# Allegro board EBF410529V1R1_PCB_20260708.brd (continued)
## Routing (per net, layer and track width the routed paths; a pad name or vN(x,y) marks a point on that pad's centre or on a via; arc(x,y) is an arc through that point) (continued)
RMII1_MDIN2: length 63.3
  TOP w0.107: v1(81.5,36.23) 81.86,35.87 81.86,33.08 81.8,33.02 U8.7
  BOTTOM w0.107: v1(81.5,36.23) 81.1,36.63 81.1,37.44 79.65,38.89 70.95,38.89 66.42,43.41 66.42,49.6 66.77,49.95 66.77,50.89 66.42,51.24 66.42,56.67 68.66,58.9 68.66,63.88 75.08,70.3 79.93,70.3 81.48,71.86 81.48,73.05 81.63,73.19 J7.6
RMII1_MDIN3: length 61.6
  TOP w0.107: U8.10 80.6,33.02 80.66,33.08 80.66,36.08 v1(80.51,36.22)
  BOTTOM w0.107: J7.9 77.82,72.97 78,73.15 78.61,73.15 78.93,72.84 78.93,71.59 78.42,71.07 74.74,71.07 67.85,64.19 67.85,59.31 65.38,56.84 65.38,43.16 70.42,38.12 79.01,38.12 80.1,37.02 80.1,36.63 v1(80.51,36.22)
RMII1_MDIP0: length 67
  TOP w0.107: v1(84.01,37.03) 84.41,36.64 84.41,33.94 84.14,33.67 84.14,33.08 84.2,33.02 U8.1
  BOTTOM w0.107: J7.2 86.71,73.13 86.84,73 86.84,71.76 86.02,70.94 85.13,70.94 84.29,70.1 82.54,70.1 80.92,68.47 75.84,68.47 70.49,63.12 70.49,58.12 68.34,55.98 68.34,52.51 68.83,52.02 68.83,48.87 68.34,48.38 68.34,44.56 72,40.9 80.97,40.9 83.89,37.98 83.89,37.14 83.99,37.03 v1(84.01,37.03)
RMII1_MDIP1: length 72.4
  TOP w0.107: v1(83.01,37.03) 83.41,36.63 83.41,33.94 82.93,33.46 82.93,33.09 83,33.02 U8.4
  BOTTOM w0.107: v1(83.01,37.03) 82.89,37.16 82.89,37.58 80.43,40.04 71.6,40.04 67.57,44.06 67.57,48.98 67.97,49.38 67.97,51.51 67.57,51.91 67.57,56.3 69.71,58.44 69.71,63.44 75.52,69.25 80.44,69.25 82.11,70.92 83.74,70.92 84.31,71.48 84.31,72.86 83.06,74.11 83.06,75.37 83.44,75.74 85.27,75.74 85.45,75.56 85.45,74.27 85.24,74.07 84.38,74.07 84.17,74.28 J7.4
RMII1_MDIP2: length 63.4
  TOP w0.107: U8.6 82.2,33.02 82.14,33.08 82.14,36.4 v1(81.51,37.03)
  BOTTOM w0.107: v1(81.51,37.03) 81.49,37.03 81.39,37.14 81.39,37.56 79.77,39.17 71.06,39.17 66.71,43.53 66.71,49.48 67.06,49.83 67.06,51 66.71,51.35 66.71,56.55 68.94,58.78 68.94,63.76 75.2,70.02 80.05,70.02 81.77,71.74 81.77,72.91 81.96,73.1 82.73,73.1 82.9,72.93 J7.5
RMII1_MDIP3: length 61.7
  TOP w0.107: v1(80.51,37.03) 80.94,36.6 80.94,33.08 81,33.02 U8.9
  BOTTOM w0.107: J7.8 78.84,74.5 78.84,73.33 79.21,72.95 79.21,71.47 78.53,70.79 74.85,70.79 68.13,64.07 68.13,59.19 65.66,56.72 65.66,43.28 70.54,38.4 79.13,38.4 80.49,37.03 v1(80.51,37.03)
RMII1_VDD10: length 34.4
  TOP w0.203: v1(85.95,31.19) 85.68,30.92 U8.38 ; U8.8 v1(81.4,33.23) ; U8.3 v1(83.4,33.23) ; C56.1 79.83,26.11 80.6,26.88 U8.21
  TOP w0.254: C56.1 78.19,26.37 v1(78.19,26.86)
  ART03 w0.254: v1(86.2,20.19) 86.2,21.8 81.14,26.86 v1(78.19,26.86)
  BOTTOM w0.254: v1(78.19,26.86) 79.01,26.86 79.55,27.41 79.55,30.2 79.04,30.71 79.04,32.25 79.55,32.76 80.92,32.76 v1(81.4,33.23) 81.91,32.72 C53.1 C55.1 82.9,32.73 v1(83.4,33.23) 83.9,32.73 85.36,32.73 85.95,32.13 v1(85.95,31.19)
ROUT1: length 42.2
  TOP w0.203: v1(47.52,67.26) 53.04,67.26 54.18,68.4 54.18,70.89 53.03,72.03 C82.2
  ART03 w0.203: v1(24.69,61.43) 25.42,61.43 25.7,61.72 25.7,63.95 26.16,64.41 26.16,65.3 28.25,67.39 31.42,67.39 31.93,66.88 35.56,66.88 36.75,65.68 45.8,65.68 47.37,67.26 v1(47.52,67.26)
  BOTTOM w0.107: U9.11 24.69,61.41 v1(24.69,61.43)
ROUT2: length 20
  BOTTOM w0.254: U9.14 26.46,62.06 26.46,64.21 27.19,64.93 27.19,65.43 26.83,65.79 19.91,65.79 19.18,66.52 17.48,66.52 17.12,66.88 17.12,71.25 17.37,71.5 C211.1
RS232_R1IN: length 13.5
  TOP w0.254: U33.13 55.17,17.02 54.51,16.36 54.51,8.71 51.97,6.17 J24.4
RS232_R1OUT: length 86.8
  TOP w0.254: U33.12 v1(55.01,15.74)
  ART03 w0.254: v1(55.01,15.74) 57.43,13.32 57.43,11.02 57.94,10.52 66.4,10.52 71.58,5.33 116.18,5.33 117.2,6.35 132.2,6.35 132.99,5.56 J27.1
RS232_R2IN: length 19.2
  TOP w0.254: U33.8 v1(52.18,11.94)
  ART03 w0.254: J24.1 61.99,4.65 54.41,4.65 53.52,5.54 53.52,7.09 52.18,8.43 v1(52.18,11.94)
RS232_R2OUT: length 78.5
  TOP w0.254: U33.9 v1(55.01,11.94)
  ART03 w0.254: J28.1 123.72,3.25 118.75,3.25 118.41,2.92 67.94,2.92 66.33,4.53 66.33,7.33 65.23,8.43 56.54,8.43 55.01,9.96 v1(55.01,11.94)
RS232_T1IN: length 87.9
  TOP w0.254: U33.11 v1(55.01,14.48)
  ART03 w0.254: J27.2 131.65,3.28 131.65,4.9 130.99,5.56 118.21,5.56 117.27,4.62 70.79,4.62 65.99,9.42 57.23,9.42 56.36,10.29 56.36,13.13 v1(55.01,14.48)
RS232_T1OUT: length 21.2
  TOP w0.254: J24.6 45.97,7.67 50.62,7.67 53.7,10.74 53.7,17.77 54.2,18.28 U33.14
RS232_T2IN: length 81.9
  TOP w0.254: U33.10 v1(55.01,13.2)
  ART03 w0.254: J28.2 123.94,0.94 118.87,0.94 117.63,2.18 67.01,2.18 65.25,3.94 65.25,6.89 64.64,7.49 56.13,7.49 54.15,9.47 54.15,12.34 v1(55.01,13.2)
RS232_T2OUT: length 10
  TOP w0.254: U33.7 v1(52.18,13.2)
  ART03 w0.254: J24.3 53.01,8.82 53.01,12.37 v1(52.18,13.2)
RS485_1_3V3: length 12.8
  TOP w0.254: D41.2 41.63,12.86 41.63,20.22 41.03,20.82 U36.8
  TOP w0.381: U36.8 v1(39.18,20.82)
  BOTTOM w0.381: v1(39.18,20.82) 39.05,20.69 C198.1 L16.2
RS485_1_A: length 26.7
  TOP w0.254: R211.2 38.47,14.77 38.93,14.31 DN1.2 38.23,11.02 38.23,9.91 40.64,7.5 40.64,4.57 40.08,4.01 36.98,4.01 36.43,4.57 36.43,5.54 35.92,6.05 J31.2 ; R211.2 38.23,15.74 38.23,18.24 38.58,18.59 39.27,18.59 39.58,18.28 U36.6 ; R211.2 R213.1
RS485_1_B: length 25.6
  TOP w0.254: U36.7 39.67,19.55 39.29,19.18 38.53,19.18 37.72,18.36 37.72,15.74 R211.1 ; R214.1 R211.1 ; R211.1 37.47,14.77 37.02,14.31 DN1.1 37.72,11.02 37.72,9.7 40.13,7.29 40.13,4.9 39.75,4.52 37.32,4.52 36.94,4.9 36.94,5.54 37.45,6.05 J31.1
RS485_1_DIR: length 75
  TOP w0.107: J3.180 61.19,65.61 v1(61.2,65.61) ; v1(55.56,65.61) 56.13,65.03 56.13,53.66 53.29,50.82 53.29,27.23 48.13,22.07 37.57,22.07 36.69,21.19 v1(36.69,19.55) U36.2 34.39,19.55 34.16,19.33 34.16,18.47 34.34,18.29 35.43,18.29 U36.3
  BOTTOM w0.107: v1(55.56,65.61) 56.47,64.69 60.28,64.69 v1(61.2,65.61)
  BOTTOM w0.254: R212.1 36.69,20.04 v1(36.69,19.55)
RS485_2_3V3: length 12.9
  TOP w0.254: D42.2 49.28,12.89 49.28,20.29 48.75,20.82 U37.8
  TOP w0.381: U37.8 v1(46.84,20.82)
  BOTTOM w0.381: v1(46.84,20.82) 46.71,20.69 C199.1 L17.2
RS485_2_A: length 39.3
  TOP w0.254: R216.2 46.09,14.77 46.55,14.31 DN2.2 45.85,11.02 45.85,10.41 42.75,7.31 42.75,3.42 41.96,2.64 29.54,2.64 28.81,3.37 28.81,5.54 28.3,6.05 J31.4 ; R216.2 R215.1 ; R216.2 45.85,15.74 45.85,18.23 46.28,18.66 47.1,18.66 47.48,18.28 U37.6
RS485_2_B: length 38.3
  TOP w0.254: J31.3 29.83,6.05 29.32,5.54 29.32,3.65 29.83,3.15 41.73,3.15 42.24,3.65 42.24,7.52 45.34,10.62 45.34,11.02 DN2.1 44.64,14.31 45.09,14.77 R216.1 ; R218.1 R216.1 ; R216.1 45.34,15.74 45.34,18.44 46.07,19.17 47.11,19.17 47.49,19.55 U37.7
RS485_2_DIR: length 64.5
  TOP w0.107: v1(44.35,19.55) 44.37,19.53 44.37,18.44 44.22,18.28 U37.3 ; v1(44.35,19.55) U37.2 ; v1(44.35,19.55) 44.35,21.4 44.56,21.62 48.36,21.62 53.77,27.03 53.77,50.75 56.46,53.44 56.46,65.51 v1(56.56,65.61) ; J3.178 60.69,65.12 v1(60.2,65.61)
  BOTTOM w0.107: v1(56.56,65.61) 57.04,65.13 59.71,65.13 v1(60.2,65.61)
  BOTTOM w0.254: R217.1 44.35,20.04 v1(44.35,19.55)
RTC_INT: length 137
  TOP w0.107: v1(59.2,65.61) 59.99,66.41 71.24,66.41 71.69,65.95 J3.222 ; v1(20.48,18.54) 21.46,17.55 26.37,17.55 27.72,18.9 27.72,21.67 28.47,22.42 47.94,22.42 52.83,27.32 52.83,50.85 55.8,53.82 55.8,64.79 55.46,65.13 55.04,65.13 v1(54.56,65.61)
  BOTTOM w0.107: D18.2 9.85,47.45 9.64,47.24 R156.2 10.59,46.99 10.95,47.35 15.65,47.35 17.09,45.9 17.09,43.95 19.99,41.05 19.99,19.28 20.48,18.79 v1(20.48,18.54) ; v1(54.56,65.61) 54.97,66.02 58.79,66.02 v1(59.2,65.61)
SAI1_LRCK_M0: length 6.4
  TOP w0.132: v1(22.26,60.44) 22.76,60.94 22.76,61.7 23.19,62.13 J3.36
  BOTTOM w0.132: v1(22.26,60.44) 22.84,60.44 U9.7
SAI1_MCLK_M0: length 15.6
  TOP w0.132: J3.34 22.69,62.26 22.26,61.83 v1(22.26,61.44)
  BOTTOM w0.132: U9.1 24.37,55.22 21.49,55.22 20.83,55.88 20.83,60.77 21.04,60.99 21.81,60.99 v1(22.26,61.44)
SAI1_SCLK_M0: length 8
  TOP w0.132: J3.38 23.69,62.02 23.25,61.58 23.25,60.33 22.81,59.89 22.81,58.88 v1(23.26,58.44)
  BOTTOM w0.132: U9.5 24.94,58.34 24.46,57.86 23.93,57.86 23.35,58.44 v1(23.26,58.44)
SAI1_SDI0_M0: length 4.4
  TOP w0.107: v1(24.08,60.75) 24.08,61.41 24.69,62.03 J3.42
  BOTTOM w0.107: U9.8 23.91,60.28 23.91,60.59 v1(24.08,60.75)
SAI1_SDO2_M0: length 6.8
  TOP w0.107: J3.40 24.19,61.96 23.65,61.42 23.65,59.82 23.26,59.44 v1(23.26,59.41)
  BOTTOM w0.107: v1(23.26,59.41) 23.26,59.11 23.98,58.39 24.36,58.39 U9.6
SARADC_IN3: length 109.8
  TOP w0.107: R207.1 86.51,16.35 86.51,12.14 v1(86.74,11.91) ; v1(49.19,59.25) 48.21,60.23 42.76,60.23 41.32,61.67 40.44,61.67 40.19,61.92 v1(40.19,62.44) J3.104
  BOTTOM w0.107: v1(49.19,59.25) 49.19,58.82 48.46,58.09 48.46,57.18 48.11,56.82 47.05,56.82 44.93,54.69 44.93,52.84 47.5,50.27 47.5,34.19 46.55,33.24 46.55,28.4 50.24,24.71 50.24,12.93 52.45,10.72 75.81,10.72 77.08,12 77.31,12.22 79.35,12.22 80.22,13.09 85.56,13.09 v1(86.74,11.91) ; v1(40.19,62.44) 40.12,62.37 R16.1 R15.2
SARADC_IN5: length 106
  TOP w0.107: v1(48.19,59.25) 47.47,59.97 42.54,59.97 41.32,61.2 40.29,61.2 39.69,61.8 J3.102 ; R208.1 84.76,16.32 84.76,12.11 v1(84.96,11.91)
  BOTTOM w0.107: v1(84.96,11.91) 84.17,12.7 80.54,12.7 79.68,11.84 77.47,11.84 75.97,10.34 52.22,10.34 49.83,12.73 49.83,24.54 46.13,28.25 46.13,33.48 47.09,34.44 47.09,36.75 46.48,37.36 46.48,38.05 47.11,38.68 47.11,50.11 44.54,52.68 44.54,54.85 48.19,58.5 v1(48.19,59.25)
SARADC_IN6: length 104
  TOP w0.107: R209.1 82.95,16.35 82.95,12.14 v1(83.19,11.91) ; v1(47.19,59.25) 46.73,59.72 42.29,59.72 41.07,60.94 40.08,60.94 39.19,61.82 J3.100
  BOTTOM w0.107: v1(83.19,11.91) 82.8,12.29 80.95,12.29 80.11,11.45 77.72,11.45 76.2,9.93 52.02,9.93 49.45,12.5 49.45,24.34 45.74,28.05 45.74,33.64 46.71,34.6 46.71,36.59 46.1,37.2 46.1,38.21 46.73,38.84 46.73,48.88 45.75,49.86 45.75,50.88 44.15,52.47 44.15,55.07 47.19,58.11 v1(47.19,59.25)
SARADC_IN7: length 102.7
  TOP w0.107: v1(46.69,58.25) 45.49,59.46 42.04,59.46 40.82,60.68 39.76,60.68 38.69,61.75 J3.98 ; R210.1 81.17,16.35 81.17,12.14 81.43,11.88 v1(81.43,11.84)
  BOTTOM w0.107: v1(46.69,58.25) 43.76,55.32 43.76,52.1 44.68,51.18 44.68,50.16 45.65,49.2 45.65,36.98 46.25,36.37 46.25,34.7 45.14,33.58 45.14,27.38 45.47,27.05 45.47,24.21 45.87,23.8 47.31,23.8 49.06,22.05 49.06,12.25 51.84,9.47 76.45,9.47 78.04,11.06 80.66,11.06 v1(81.43,11.84)
SDMMC0_CLK: length 119.2
  TOP w0.132: J3.164 v1(55.19,61.44)
  BOTTOM w0.132: v1(55.19,61.44) 55.3,61.34 55.3,30.29 61.34,24.24 70.18,24.24 70.83,23.6 71.57,23.6 71.73,23.44 71.73,22.76 71.86,22.63 72.26,22.63 72.39,22.76 72.39,23.44 72.62,23.67 77.34,23.67 77.58,23.44 77.58,23.09 77.71,22.96 78.1,22.96 78.24,23.09 78.24,23.44 78.37,23.57 78.76,23.57 78.9,23.44 78.9,23.09 79.03,22.96 79.42,22.96 79.56,23.09 79.56,23.44 79.69,23.57 80.09,23.57 80.22,23.44 80.22,23.09 80.35,22.96 80.75,22.96 80.88,23.09 80.88,23.44 81.01,23.57 81.41,23.57 81.54,23.44 81.54,23.09 81.67,22.96 82.07,22.96 82.2,23.09 82.2,23.44 82.33,23.57 82.73,23.57 82.86,23.44 82.86,23.09 82.99,22.96 83.39,22.96 83.52,23.09 83.52,23.44 83.73,23.65 90.25,23.65 90.86,23.04 106.24,23.04 106.37,23.17 106.37,23.54 106.5,23.67 106.9,23.67 107.03,23.54 107.03,23.17 107.16,23.04 119.3,23.04 120.51,21.83 126.68,21.83 127.69,20.83 128.5,20.83 128.91,20.41 R20.1
SDMMC0_CMD: length 119.7
  TOP w0.132: J3.158 v1(53.69,62.44)
  BOTTOM w0.132: R19.1 128.42,17.4 125.73,20.09 125.73,20.95 125.27,21.42 120.34,21.42 119.24,22.52 90.48,22.52 89.99,23.01 84.25,23.01 84.02,22.78 84.02,22.3 83.81,22.09 77.02,22.09 76.89,22.22 76.89,22.91 76.76,23.04 76.36,23.04 76.23,22.91 76.23,22.22 76.1,22.09 75.7,22.09 75.57,22.22 75.57,22.91 75.44,23.04 75.04,23.04 74.91,22.91 74.91,22.22 74.78,22.09 74.33,22.09 74.19,22.23 74.19,22.86 74.01,23.05 73.11,23.05 72.95,22.89 72.95,22.28 72.76,22.09 71.46,22.09 69.72,23.83 61.17,23.83 54.81,30.19 54.81,60.2 53.69,61.32 v1(53.69,62.44)
SDMMC0_D0: length 121.6
  TOP w0.132: J3.160 v1(54.19,61.44)
  BOTTOM w0.132: v1(54.19,61.44) 54.68,61.93 55.35,61.93 55.78,61.49 55.78,30.42 61.54,24.65 70.6,24.65 70.99,24.26 90.53,24.26 91.21,23.57 99.23,23.57 99.36,23.7 99.36,24.38 99.49,24.51 99.89,24.51 100.02,24.38 100.02,23.7 100.15,23.57 100.41,23.57 100.54,23.7 100.54,24.43 100.68,24.56 101.07,24.56 101.2,24.43 101.2,23.7 101.34,23.57 101.73,23.57 101.87,23.7 101.87,24.43 102,24.56 102.39,24.56 102.53,24.43 102.53,23.7 102.66,23.57 103.05,23.57 103.19,23.7 103.19,24.43 103.32,24.56 103.71,24.56 103.85,24.43 103.85,23.7 103.98,23.57 104.38,23.57 104.51,23.7 104.51,24.43 104.64,24.56 105.04,24.56 105.17,24.43 105.17,23.7 105.3,23.57 105.7,23.57 105.83,23.7 105.83,24.43 105.96,24.56 106.91,24.56 107.82,23.65 121.79,23.65 123.2,22.24 128.39,22.24 R23.1
SDMMC0_D1: length 121.1
  TOP w0.132: J3.162 v1(54.69,62.44)
  BOTTOM w0.132: R24.1 128.73,22.67 123.35,22.67 121.84,24.18 108,24.18 107.12,25.06 98.67,25.06 98.53,24.93 98.53,24.39 98.4,24.26 98,24.26 97.87,24.39 97.87,24.93 97.74,25.06 97.34,25.06 97.21,24.93 97.21,24.39 97.08,24.26 96.68,24.26 96.55,24.39 96.55,24.93 96.42,25.06 96.02,25.06 95.89,24.93 95.89,24.39 95.76,24.26 95.36,24.26 95.23,24.39 95.23,24.93 95.1,25.06 94.7,25.06 94.57,24.93 94.57,24.39 94.44,24.26 94.04,24.26 93.91,24.39 93.91,24.93 93.78,25.06 93.38,25.06 93.25,24.93 93.25,24.39 93.12,24.26 92.72,24.26 92.59,24.39 92.59,24.93 92.46,25.06 92.06,25.06 91.93,24.93 91.93,24.39 91.8,24.26 91.4,24.26 91.27,24.39 91.27,24.93 91.14,25.06 89.45,25.06 89.2,24.82 88.79,24.82 88.54,25.06 88.13,25.06 87.88,24.82 87.47,24.82 87.22,25.06 86.8,25.06 86.56,24.82 86.14,24.82 85.9,25.06 85.48,25.06 85.23,24.82 84.82,24.82 84.57,25.06 84.16,25.06 83.91,24.82 83.5,24.82 83.25,25.06 82.84,25.06 82.59,24.82 82.18,24.82 81.98,25.02 81.47,25.02 81.27,24.82 80.86,24.82 80.63,25.04 80.18,25.04 79.95,24.82 79.54,24.82 79.29,25.06 78.88,25.06 78.63,24.82 78.22,24.82 77.97,25.06 77.56,25.06 77.31,24.82 76.9,24.82 76.65,25.06 76.24,25.06 75.99,24.82 75.58,24.82 75.35,25.04 74.89,25.04 74.67,24.82 74.25,24.82 74.03,25.04 73.57,25.04 73.35,24.82 72.93,24.82 72.71,25.04 72.25,25.04 72.02,24.82 71.61,24.82 71.36,25.06 61.71,25.06 56.29,30.49 56.29,61.77 55.62,62.44 v1(54.69,62.44)
SDMMC0_D2: length 116.3
  TOP w0.132: J3.154 52.69,62.44 52.69,62.44 v1(52.69,62.1)
  BOTTOM w0.132: v1(52.69,62.1) 52.69,61.05 53.9,59.84 53.9,29.94 60.87,22.96 68.86,22.96 70.84,20.98 90.14,20.98 90.68,21.51 119.07,21.51 120,20.59 123.99,20.59 128.24,16.33 128.24,15.78 R17.1
SDMMC0_D3: length 119.7
  TOP w0.132: v1(53.19,61.44) 53.44,61.69 53.44,62.03 53.19,62.28 J3.156
  BOTTOM w0.132: R18.1 125.22,19.95 125.22,20.7 124.92,21 120.17,21 119.18,22 90.27,22 89.97,21.69 89.6,21.69 89.35,21.95 88.94,21.95 88.69,21.69 88.39,21.69 88.26,21.82 88.26,22.35 88.13,22.48 87.73,22.48 87.6,22.35 87.6,21.75 87.47,21.62 87.07,21.62 86.94,21.75 86.94,22.35 86.81,22.48 86.41,22.48 86.28,22.35 86.28,21.82 86.15,21.69 85.75,21.69 85.64,21.81 85.64,22.34 85.45,22.53 85.16,22.53 84.99,22.35 84.99,21.97 84.53,21.51 71.15,21.51 69.24,23.42 61,23.42 54.36,30.06 54.36,59.99 53.19,61.16 v1(53.19,61.44)
SDMMC0_DETN: length 115.6
  TOP w0.132: J3.152 v1(52.19,61.44)
  BOTTOM w0.132: R25.1 127.58,24 126.67,23.09 123.55,23.09 121.89,24.75 108.02,24.75 107.29,25.48 61.95,25.48 56.77,30.66 56.77,62.23 56.13,62.87 52.71,62.87 52.19,62.35 v1(52.19,61.44)
SIM_CLK0: length 75.1
  TOP w0.132: J20.12 118.82,20.01 118.23,20.61 v1(117.6,20.61)
  ART03 w0.152: v1(134.06,42.01) 134.06,31.4 136.45,29.01 146.51,29.01 147.85,27.66 147.85,18.09 146.89,17.12 138.73,17.12 137.72,18.14 129.54,18.14 128.5,19.18 119.04,19.18 v1(117.6,20.61)
  BOTTOM w0.132: R174.1 133.46,42.01 v1(134.06,42.01)
SIM_DATA0: length 79.7
  TOP w0.132: v1(117.25,17.34) 117.76,17.34 118.02,17.61 J20.10
  ART03 w0.152: v1(117.25,17.34) 118.58,18.67 128.32,18.67 129.29,17.7 137.44,17.7 138.51,16.64 147.19,16.64 148.29,17.73 148.29,28.09 146.94,29.44 136.63,29.44 134.49,31.58 v1(134.49,43.01)
  BOTTOM w0.132: R175.1 132.17,43.01 v1(134.49,43.01)
SIM_RST0: length 63.6
  TOP w0.132: J20.14 119.62,19.76 v1(119.33,20.06)
  ART03 w0.152: v1(133.58,33.2) 133.58,31.27 136.27,28.57 146.13,28.57 147.42,27.28 147.42,18.47 146.58,17.63 139.04,17.63 138.02,18.64 129.74,18.64 128.78,19.61 119.78,19.61 v1(119.33,20.06)
  BOTTOM w0.132: v1(133.58,33.2) 128.55,33.2 128.28,33.47 R173.1
SIM_VDD: length 86.9
  TOP w0.254: J20.8 117.22,19.8 116.97,20.06 v1(116.62,20.06)
  TOP w0.305: v1(131.11,35.82) 131.86,35.82 v1(132.8,34.87)
  ART03 w0.254: v1(116.62,20.06) 116.62,17.26 117.07,16.81 117.93,16.81 118.82,17.7 127.81,17.7 128.71,16.81 131.25,16.81 131.7,16.36 136.98,16.36 137.59,15.75 139.85,15.75 140.16,16.05 147.45,16.05 148.77,17.37 148.77,28.55 147.4,29.92 136.98,29.92 135.89,31.01 v1(135.89,31.27)
  BOTTOM w0.305: v1(131.11,35.82) U27.1 130.51,35.81 128.52,35.81 128.28,36.06 R171.1 127.41,36.83 127.05,36.47 127.05,32.74 127.58,32.21 128.93,32.21 129.87,31.27 v1(135.89,31.27) ; v1(132.8,34.87) 133.59,34.09 J19.1
SPI1_CLK_M0: length 126.9
  TOP w0.132: v1(59.69,62.44) 59.69,62.44 J3.174
  BOTTOM w0.132: v1(59.69,62.44) 59.69,61.09 59.49,60.88 59.49,59.31 59,58.82 59,37.9 62.31,34.59 69.33,34.59 71.22,36.47 77.19,36.47 79.07,34.59 85.82,34.59 86.71,35.48 105.11,35.48 108.79,39.17 108.79,41 111.07,43.28 116.94,43.28 118.29,44.63 130.35,44.63 131.78,46.05 142.57,46.05 144.32,47.8 145.8,47.8 146.05,48.06 146.05,50.39 J32.12
SPI1_CSN1_M0: length 124.3
  TOP w0.107: J3.168 v1(58.19,61.44)
  BOTTOM w0.107: v1(58.19,61.44) 58.19,36.88 61.16,33.91 69.81,33.91 70.75,34.85 77.62,34.85 78.57,33.9 86.14,33.9 86.97,34.74 105.55,34.74 109.55,38.73 109.55,40.56 111.48,42.5 117.79,42.5 118.98,43.69 130.58,43.69 131.98,45.09 145.82,45.09 J32.16
SPI1_MISO_M0: length 121.7
  TOP w0.107: J3.172 v1(59.19,61.44)
  BOTTOM w0.107: v1(59.19,61.44) 58.6,60.85 58.6,37.72 62.13,34.19 69.54,34.19 71.4,36.05 77.01,36.05 78.87,34.19 86,34.19 86.89,35.08 105.36,35.08 109.22,38.94 109.22,40.79 111.3,42.88 117.32,42.88 118.54,44.09 130.43,44.09 131.9,45.57 143.76,45.57 J32.15
SPI1_MOSI_M0: length 122.5
  TOP w0.107: J3.176 60.19,62.65 60.4,62.44 v1(60.69,62.44)
  BOTTOM w0.107: J32.13 142.16,46.51 131.62,46.51 130.18,45.06 117.88,45.06 116.51,43.69 110.52,43.69 107.75,40.92 107.75,39.37 104.31,35.94 86.58,35.94 85.65,35 79.35,35 77.42,36.93 71.04,36.93 69.1,34.99 62.49,34.99 59.44,38.05 59.44,58.62 59.74,58.93 60.76,58.93 61.16,59.33 61.16,61.97 v1(60.69,62.44)
SPK_CTRL: length 52.5
  TOP w0.107: v1(43.69,62.44) 43.98,62.44 44.19,62.65 J3.120 ; v1(19.94,65.15) 19.43,65.66 17.73,65.66 17.32,66.07 17.32,68.1 17.57,68.35 ; v1(17.92,68.35) 17.57,68.35 ; 17.57,68.35 17.37,68.55 17.37,70.95 R102.1
  BOTTOM w0.107: R225.1 v1(17.92,68.35) ; v1(19.94,65.15) 19.86,65.07 19.86,55.42 21.01,54.26 31.81,54.26 33.96,56.41 33.96,58.8 35.21,60.05 35.21,62.13 36.58,63.5 42.63,63.5 v1(43.69,62.44)
SPK_LN: length 53.9
  TOP w0.381: v1(24.41,67.51) 24.99,66.93 32.38,66.93 32.77,67.31 C205.1 32.76,67.69 L18.2
  ART03 w0.203: J9.1 37.98,81.7 37.98,81.41 37.23,80.66 35.8,80.66 34.87,79.73 31.24,79.73 30.33,78.82 24.49,78.82 23.57,79.73 20.58,79.73 18.26,77.41 18.26,73.79 18.57,73.49 18.57,69.24 20.9,66.9 20.9,66.45 21.36,65.99 22.48,65.99 23.2,66.71 23.2,69.09 23.45,69.34 23.98,69.34 24.18,69.14 24.18,67.74 v1(24.41,67.51)
SPK_LP: length 53.5
  TOP w0.381: L19.2 32.76,71.5 C90.1 32.77,71.88 32.38,72.26 24.99,72.26 v1(24.38,71.65)
  ART03 w0.203: v1(24.38,71.65) 24.16,71.42 24.16,69.93 23.95,69.72 23.3,69.72 22.82,69.25 22.82,66.85 22.31,66.35 21.54,66.35 21.29,66.6 21.29,67.03 18.92,69.39 18.92,73.63 18.62,73.94 18.62,77.27 20.73,79.37 23.42,79.37 24.33,78.46 30.48,78.46 31.39,79.37 35.02,79.37 35.95,80.31 37.38,80.31 38.43,81.36 38.43,81.59 J9.2
SPK_RN: length 42.9
  ART03 w0.203: v1(22.05,72.1) 22.05,70.87 21.65,70.46 20.65,70.46 20.24,70.87 20.24,74.47 19.95,74.76 19.95,76.77 21.26,78.08 22.71,78.08 23.93,76.86 30.96,76.86 32.18,78.08 36.16,78.08 36.39,78.3 37.45,78.3 37.8,77.95 37.8,77.38 J22.1
  BOTTOM w0.381: v1(22.05,72.1) 22.22,72.26 32.38,72.26 32.77,71.88 C214.1 32.76,71.5 L20.2
SPK_RP: length 46.5
  ART03 w0.203: v1(22.05,67.1) 22.06,67.1 22.06,69.7 21.65,70.1 20.5,70.1 19.89,70.71 19.89,74.32 19.6,74.61 19.6,76.92 21.11,78.44 22.86,78.44 24.05,77.24 30.78,77.24 31.98,78.44 36.02,78.44 36.24,78.66 37.59,78.66 38.18,78.07 38.18,77.5 38.84,76.84 J22.2
  BOTTOM w0.381: v1(22.05,67.1) 22.22,66.93 32.38,66.93 32.77,67.31 C213.1 32.76,67.69 L21.2
SUB1: length 11
  TOP w0.135: J10.A8 27.05,82.32 27.1,82.28 v1(27.1,82.25)
  BOTTOM w0.135: C105.1 23.5,78.34 arc(23.43,78.46) 23.4,78.59 23.4,78.62 arc(23.43,78.75) 23.5,78.87 R123.1 23.5,79.38 arc(23.43,79.49) 23.4,79.62 23.4,79.64 arc(23.43,79.77) 23.5,79.88 R119.1 23.49,80.4 arc(23.42,80.51) 23.4,80.63 23.4,80.72 arc(23.41,80.79) 23.45,80.84 23.54,80.93 arc(23.66,81.01) 23.81,81.04 24.83,81.04 arc(25.54,81.34) 25.84,82.05 25.84,83.36 arc(25.86,83.45) 25.91,83.52 25.93,83.55 arc(26,83.6) 26.09,83.61 26.37,83.61 arc(26.43,83.6) 26.49,83.57 26.5,83.55 arc(26.54,83.5) 26.55,83.44 D23.2 27.1,82.38 v1(27.1,82.25)
SUB2: length 13.3
  TOP w0.107: v1(28.8,85.35) J10.B8
  BOTTOM w0.135: C106.1 22.74,78.1 arc(22.99,78.2) 23.09,78.44 23.09,78.51 arc(23.04,78.74) 22.92,78.93 R124.1 23,79.39 arc(23.06,79.49) 23.09,79.62 23.09,79.64 arc(23.06,79.76) 23,79.87 R122.1 22.94,80.36 arc(23.05,80.51) 23.08,80.7 23.08,80.72 arc(23.12,80.91) 23.23,81.06 23.31,81.15 arc(23.54,81.3) 23.81,81.36 24.83,81.36 arc(25.32,81.56) 25.53,82.05 25.53,83.36 arc(25.57,83.57) 25.68,83.74 25.71,83.77 arc(25.88,83.89) 26.09,83.93 27.2,83.93 arc(27.7,84.03) 28.12,84.31 28.42,84.61 arc(28.54,84.68) 28.67,84.71 D24.2 28.84,85.32 v1(28.8,85.35)
SYS_LED: length 204
  TOP w0.107: v1(71.6,82.88) v1(73.1,82.88) ; v1(129.27,56.11) 129.27,52.06 137.72,43.61 137.72,38.61 136.96,37.85 136.96,29.36 137.36,28.96 144.3,28.96 145.08,28.17 147.78,28.17 148.84,27.1 148.84,9.86 147.68,8.69 142.06,8.69 141.69,8.31 LED2.1 ; v1(54.9,67.73) 53.06,65.89 44.4,65.89 43.69,65.18 J3.118
  BOTTOM w0.107: v1(71.6,82.88) 71.45,83.03 58.6,83.03 58.17,83.46 55.35,83.46 54.51,82.63 54.51,80.17 52.93,78.59 52.93,75.82 54.41,74.35 54.41,68.22 v1(54.9,67.73) ; v1(129.27,56.11) 128.68,56.7 113.15,56.7 109.78,60.07 109.78,67.16 109.28,67.66 109.28,69.13 106.54,71.87 106.54,72.58 104.29,74.83 104.29,83.34 102.36,85.27 94.03,85.27 92.3,83.54 73.76,83.54 v1(73.1,82.88)
TYPEC_CC1: length 44.9
  TOP w0.107: J10.A5 v1(28.55,82.2)
  ART03 w0.107: v1(51.75,87.79) 51.73,87.81 51.36,87.81 49.48,85.93 35.32,85.93 v1(34.95,85.56)
  BOTTOM w0.107: v1(34.95,85.56) 34.64,85.56 34.19,85.12 34.19,82.55 33.43,81.79 30.74,81.79 D21.2 28.94,82.69 28.55,82.3 v1(28.55,82.2) ; 49.04,72.76 U11.10 ; U11.11 49.34,74.71 C96.1 50.57,75.95 50.57,78.51 52.4,80.34 52.4,87.48 52.09,87.79 v1(51.75,87.79)
TYPEC_CC2: length 44.6
  TOP w0.107: v1(27.34,85.47) 27.31,85.44 J10.B5
  ART03 w0.107: v1(34.95,86.56) 35.26,86.26 49.4,86.26 50.75,87.61 v1(50.75,88.29)
  BOTTOM w0.107: v1(34.95,86.56) 34.26,86.56 33.88,86.18 29.79,86.18 29.46,85.85 27.72,85.85 v1(27.34,85.47) 27.55,85.26 D22.2 ; v1(50.75,88.29) 52.52,88.29 52.73,88.08 52.73,80.29 50.88,78.44 50.88,75.95 C95.1 51.38,73.69
TYPEC_DM: length 17
  TOP w0.135: J10.A7 27.65,82.97 27.65,81.97 arc(27.62,81.81) 27.53,81.67 v1(27.38,81.53) 27.53,81.39 arc(27.62,81.26) 27.65,81.1 27.65,80.25 arc(27.62,80.12) 27.55,80 D20.2 27.61,79.69 arc(27.74,79.5) 27.78,79.28 27.78,78.68 arc(27.74,78.47) 27.62,78.28 R108.1 ; J10.B7 28.31,85.1 28.22,85.19 28.22,85.51 arc(28.17,85.78) 28.02,86 27.67,86.35 arc(27.5,86.61) 27.44,86.91 27.44,87.2 arc(27.45,87.27) 27.5,87.33 27.57,87.41 27.68,87.41 arc(27.75,87.4) 27.81,87.36 v1(28.01,87.15)
  ART03 w0.135: v1(27.38,81.53) 27.6,81.74 arc(27.74,81.96) 27.79,82.21 27.79,82.51 arc(27.74,82.62) 27.64,82.66 arc(27.53,82.71) 27.48,82.82 27.48,83.18 arc(27.53,83.29) 27.64,83.34 arc(27.74,83.38) 27.79,83.49 27.79,83.86 arc(27.74,83.97) 27.64,84.01 arc(27.53,84.05) 27.48,84.16 27.48,84.53 arc(27.53,84.64) 27.64,84.68 arc(27.74,84.73) 27.79,84.84 27.79,85.51 arc(27.89,86.03) 28.19,86.48 28.48,86.77 arc(28.57,86.91) 28.6,87.07 28.6,87.27 arc(28.56,87.37) 28.47,87.41 28.43,87.41 arc(28.29,87.38) 28.17,87.3 v1(28.01,87.15)
TYPEC_DP: length 17.3
  TOP w0.135: R107.1 28.26,78.28 arc(28.14,78.47) 28.1,78.68 28.1,79.28 arc(28.14,79.5) 28.27,79.69 D19.2 28.2,80.14 arc(28.02,80.4) 27.96,80.72 27.96,81.1 arc(27.99,81.26) 28.08,81.39 v1(28.22,81.53) 28.08,81.67 arc(27.99,81.81) 27.96,81.97 27.96,82.97 J10.A6 ; v1(28.01,87.98) 27.85,87.82 arc(27.74,87.75) 27.61,87.72 27.44,87.72 27.27,87.55 arc(27.17,87.39) 27.13,87.2 27.13,86.91 arc(27.21,86.49) 27.45,86.13 27.8,85.78 arc(27.88,85.66) 27.91,85.51 27.91,85.19 27.81,85.1 J10.B6
  ART03 w0.135: v1(28.01,87.98) 28.16,87.84 arc(28.29,87.75) 28.45,87.72 28.47,87.72 arc(28.78,87.59) 28.92,87.27 28.92,87.07 arc(28.86,86.79) 28.7,86.55 28.41,86.26 arc(28.18,85.92) 28.1,85.51 28.1,81.73 arc(28.11,81.66) 28.15,81.6 v1(28.22,81.53)
TYPEC_DPTX_AUX_PUPDCTL1: length 89
  TOP w0.107: J3.283 86.44,57.22 86.23,57.43 58.35,57.43 57.1,58.68 57.1,65.07 57.71,65.68 57.71,68 55.6,70.1 55.6,71.83 54.94,72.49 54.94,75.06 53.57,76.43 42.98,76.43 40.13,79.27 39.38,79.27 v1(38.95,78.85)
  BOTTOM w0.107: v1(38.95,78.85) 36.94,78.85 35.84,77.75 35.84,75.4 34.61,74.17 27.25,74.17 26.72,74.7 26.72,75.59 25.53,76.78 25.53,79.37 R119.2
TYPEC_DPTX_AUX_PUPDCTL2: length 94.7
  TOP w0.107: v1(39.95,78.85) 42.72,76.07 53.44,76.07 54.66,74.85 54.66,72.34 55.3,71.7 55.3,69.92 57.35,67.86 57.35,65.76 56.79,65.2 56.79,58.52 58.17,57.15 85.78,57.15 85.94,56.98 J3.281
  BOTTOM w0.107: v1(39.95,78.85) 39.54,78.44 36.96,78.44 36.12,77.6 36.12,75.29 34.72,73.89 20.71,73.89 20.09,74.51 20.09,76.89 20.5,77.29 20.5,78.91 R122.2
TYPEC_SSRXN1: length 14.9
  TOP w0.135: J10.B10 29.8,84.4 29.8,85.09 29.9,85.19 29.9,85.75 arc(30.07,86.16) 30.48,86.33 32.54,86.33 arc(33.11,86.21) 33.59,85.89 33.73,85.75 arc(33.96,85.4) 34.04,85 34.04,82.51 arc(33.98,82.18) 33.79,81.9 33.77,81.88 arc(33.49,81.69) 33.16,81.62 32.72,81.62 arc(32.56,81.59) 32.42,81.5 32.36,81.44 arc(32.3,81.34) 32.28,81.24 32.28,80.97 32.37,80.88 U16.6 U16.5 32.37,78.78 arc(32.4,78.63) 32.48,78.51 R113.1
TYPEC_SSRXN2: length 5.4
  TOP w0.135: R117.1 25.76,78.37 arc(25.58,78.65) 25.51,78.98 U14.5 U14.6 25.51,80.88 25.42,80.97 25.42,81.18 arc(25.45,81.34) 25.54,81.48 25.85,81.79 arc(25.94,81.92) 25.97,82.08 25.97,82.27 26.06,82.36 J10.A10
TYPEC_SSRXP1: length 13.7
  TOP w0.135: J10.B11 30.3,85.1 30.21,85.19 30.21,85.75 arc(30.29,85.94) 30.48,86.01 32.54,86.01 arc(32.99,85.93) 33.37,85.67 33.51,85.53 arc(33.67,85.28) 33.73,85 33.73,82.51 arc(33.69,82.3) 33.57,82.12 33.55,82.1 arc(33.37,81.98) 33.16,81.94 32.72,81.94 arc(32.44,81.88) 32.2,81.72 32.14,81.66 arc(32.01,81.46) 31.96,81.24 31.96,80.97 31.87,80.88 U16.7 U16.4 31.87,78.1 R112.1
TYPEC_SSRXP2: length 5.2
  TOP w0.135: J10.A11 25.56,82.36 25.66,82.27 25.66,82.14 arc(25.64,82.04) 25.58,81.96 25.28,81.65 arc(25.15,81.46) 25.1,81.24 25.1,80.97 25.01,80.88 U14.7 U14.4 25.01,78.1 R114.1
TYPEC_SSTXN1: length 5.5
  TOP w0.135: C100.1 30.25,78.51 arc(30.34,78.63) 30.37,78.78 U16.1 U16.10 30.37,80.81 arc(30.38,80.87) 30.42,80.92 30.43,80.94 arc(30.47,80.99) 30.48,81.05 30.48,81.34 arc(30.44,81.52) 30.34,81.67 29.63,82.38 arc(29.58,82.46) 29.56,82.55 J10.A3
TYPEC_SSTXN2: length 13.9
  TOP w0.135: C102.1 23.4,78.51 arc(23.48,78.63) 23.51,78.78 U14.1 U14.10 23.51,80.88 23.6,80.97 23.6,81.21 arc(23.59,81.29) 23.54,81.36 22.83,82.07 arc(22.26,82.92) 22.07,83.92 22.07,84.97 arc(22.15,85.38) 22.38,85.72 22.48,85.83 arc(22.91,86.11) 23.42,86.22 25.3,86.22 arc(25.57,86.16) 25.81,86.01 26.04,85.77 26.04,85.53 arc(26.07,85.37) 26.16,85.24 26.18,85.22 arc(26.27,85.08) 26.3,84.92 J10.B3
TYPEC_SSTXP1: length 5.2
  TOP w0.135: C99.1 30.87,78.1 U16.2 U16.9 30.87,80.92 30.79,80.99 30.79,81.34 arc(30.73,81.64) 30.56,81.89 30.18,82.28 arc(30.09,82.4) 30.06,82.55 J10.A2
TYPEC_SSTXP2: length 12.6
  TOP w0.135: C101.1 24.01,78.1 U14.2 U14.9 24.01,80.88 23.92,80.97 23.92,81.21 arc(23.88,81.41) 23.76,81.58 23.05,82.29 arc(22.55,83.04) 22.38,83.92 22.38,84.97 arc(22.43,85.26) 22.6,85.5 22.7,85.6 arc(23.03,85.83) 23.42,85.9 25.3,85.9 arc(25.45,85.87) 25.58,85.78 25.73,85.64 25.73,85.17 25.8,85.1 J10.B2
TYPEC_VBUS_EN: length 68.4
  TOP w0.107: v1(73.52,74.92) 73.1,74.5 73.1,69.16 74.69,67.57 J3.234
  ART03 w0.107: v1(34.95,84.56) 35.99,85.6 49.61,85.6 51.33,87.33 52.02,87.33 53.16,88.47 v1(54.08,88.47)
  BOTTOM w0.107: v1(34.95,84.56) 34.95,82.02 33.52,80.59 R118.1 ; v1(73.52,74.92) 72.52,75.92 72.52,83.06 71.98,83.59 58.85,83.59 58.22,84.23 55.27,84.23 54.53,84.96 54.53,88.01 v1(54.08,88.47)
U8_RX: length 17.6
  BOTTOM w0.107: J25.3 112.48,4.57 116.54,4.57 117.78,3.33 126.76,3.33 J27.5
U8_TX: length 15.3
  BOTTOM w0.107: J27.6 126.82,3.02 117.83,3.02 117.47,2.67 114.66,2.67 J25.2
U10_RX: length 21.8
  TOP w0.107: J28.5 117.59,2.21 104.7,2.21 103.67,3.24 103.67,3.88 103.07,4.47 101.43,4.47 J26.3
U10_TX: length 17.9
  TOP w0.107: J26.2 104.44,1.94 J28.6
UART0_RX: length 3.7
  TOP w0.107: R187.2 2.66,74.69 2.66,73.75 2.45,73.54 U29.2
UART0_RX_M0_DEBUG: length 68.3
  TOP w0.107: J3.159 53.94,57.34 53.62,57.66 53.19,57.66 52.65,58.19 52.65,59.74 52.14,60.25 v1(51.69,60.25) ; U29.4 v1(3.57,73.52)
  ART03 w0.107: v1(51.69,60.25) 51.69,61.93 51.21,62.42 51.21,64.57 47.6,68.17 46.35,68.17 45.87,67.69 42.71,67.69 42.29,68.12 33.38,68.12 32.26,69.24 28.23,69.24 24.57,65.58 23.24,65.58 22.12,64.47 19.51,64.47 16.97,67.01 14.07,67.01 12.37,68.71 12.37,71.55 11.41,72.51 4.58,72.51 v1(3.57,73.52)
UART0_TX: length 2.5
  TOP w0.107: U28.4 6.23,74.17 6.48,74.42 R186.2
UART0_TX_M0_DEBUG: length 65.9
  TOP w0.107: U28.2 v1(6.36,73.52) ; v1(52.19,59.25) 52.19,58.29 53.44,57.04 J3.157
  ART03 w0.107: v1(52.19,59.25) 52.19,60.83 52.55,61.19 52.55,61.59 52.17,61.97 52.17,64.03 47.75,68.45 46.2,68.45 45.7,67.95 42.82,67.95 42.39,68.38 33.58,68.38 32.36,69.6 28.22,69.6 24.46,65.84 23.13,65.84 22.52,65.23 22.5,65.23 22.05,64.77 19.66,64.77 17.02,67.41 14.2,67.41 12.73,68.88 12.73,71.81 11.01,73.52 v1(6.36,73.52)
UART3_RX_M1: length 56.2
  TOP w0.107: v1(37.62,58.25) 38.1,58.73 38.1,59.45 37.89,59.66 28.96,59.66 27.19,61.43 J3.52 ; U36.1 v1(34.24,20.82)
  BOTTOM w0.107: v1(37.62,58.25) 37.62,57.87 37.03,57.28 37.03,54.31 36.25,53.52 36.25,42.19 35.61,41.55 35.61,37.18 34.54,36.12 34.54,30.07 35.43,29.18 35.43,23.78 34.24,22.59 v1(34.24,20.82)
UART3_TX_M1: length 60.6
  TOP w0.107: v1(34.09,17.01) U36.4 ; v1(38.62,59.25) 38.62,59.42 38.12,59.93 29.15,59.93 27.69,61.39 J3.54
  BOTTOM w0.107: v1(34.09,17.01) 34.72,17.65 34.72,22.44 35.88,23.59 35.88,29.27 34.95,30.2 34.95,35.74 36.68,37.46 36.68,53.26 37.42,54.01 37.42,57.18 38.1,57.86 38.1,58.73 v1(38.62,59.25)
UART5_RX_M0: length 60
  TOP w0.107: v1(37.74,21.49) 37.95,21.69 41.27,21.69 42.14,20.82 U37.1 ; v1(39.62,59.25) 38.43,60.45 30.31,60.45 28.69,62.06 J3.58
  BOTTOM w0.107: v1(39.62,59.25) 39.62,58.12 38.02,56.51 38.02,36.47 36.4,34.85 36.4,30.51 37.49,29.41 37.49,27.94 36.6,27.05 36.6,23.39 37.74,22.25 v1(37.74,21.49)
UART5_TX_M0: length 71.2
  TOP w0.107: U37.4 44.07,17.01 v1(44.32,16.76) ; v1(38.62,58.25) 39.04,58.67 39.04,59.44 38.29,60.19 29.32,60.19 28.19,61.32 J3.56
  ART03 w0.107: v1(35.06,16.36) 35.92,15.49 43.05,15.49 v1(44.32,16.76)
  BOTTOM w0.107: v1(35.06,16.36) 35.06,22.21 36.27,23.42 36.27,29.51 35.21,30.58 35.21,34.4 37.69,36.88 37.69,56.77 38.62,57.7 v1(38.62,58.25)
UART8_RX: length 28
  TOP w0.107: R203.2 107.13,9.08 108.92,9.08 109.94,8.06 121.81,8.06 122.36,7.51 128.84,7.51 D38.2 129.45,5.48 J27.3
UART8_RX_M2: length 91
  TOP w0.107: J3.145 50.44,54.44 50.94,53.94 v1(50.94,53.54) ; R203.1 v1(105.79,12.04)
  BOTTOM w0.107: v1(50.94,53.54) 51.23,53.25 51.23,29.88 60.38,20.74 60.38,19.84 60.83,19.38 68.56,19.38 69.3,18.64 97.41,18.64 102.72,13.34 102.72,11.79 103.28,11.23 104.98,11.23 v1(105.79,12.04)
UART8_TX: length 31.6
  TOP w0.107: J27.4 131.72,3.21 131.72,6.35 D37.2 130.24,7.82 122.56,7.82 122.06,8.32 110.04,8.32 108.97,9.4 107.57,9.4 106.93,10.03 R204.2
UART8_TX_M2: length 91.7
  TOP w0.107: v1(50.94,54.54) 50.94,54.54 J3.147 ; R204.1 v1(106.93,12.06)
  BOTTOM w0.107: v1(106.93,12.06) 106.93,12.06 106.5,12.5 105.64,12.5 104.78,11.63 103.45,11.63 103.15,11.94 103.15,13.45 97.6,19 69.59,19 68.82,19.76 61.01,19.76 60.71,20.07 60.71,20.98 51.59,30.1 51.59,53.89 v1(50.94,54.54)
UART10_RX: length 22.3
  TOP w0.107: R201.2 105.49,8.56 108.15,8.56 108.46,8.26 108.46,7.82 108.74,7.54 120.68,7.54 D40.2 121.32,5.56 J28.3
UART10_RX_M1: length 86.6
  TOP w0.107: R201.1 v1(103.63,12.06) ; v1(52.44,54.54) 52.44,54.54 J3.153
  BOTTOM w0.107: v1(52.44,54.54) 51.97,54.07 51.97,30.18 61.34,20.8 68.35,20.8 69.8,19.35 97.88,19.35 103.63,13.6 v1(103.63,12.06)
UART10_TX: length 25.8
  TOP w0.107: R202.2 106.25,8.82 108.81,8.82 109.83,7.8 121.61,7.8 122.51,6.91 D39.2 123.41,5.65 123.67,5.39 123.67,3.21 J28.4
UART10_TX_M1: length 86.9
  TOP w0.107: v1(104.55,12.06) 104.65,11.96 R202.1 ; v1(52.48,53.54) 52.94,54.01 J3.155
  BOTTOM w0.107: v1(52.48,53.54) 52.48,30.1 61.4,21.17 68.59,21.17 70,19.76 98.09,19.76 104.55,13.31 v1(104.55,12.06)
USB2_OTG0_DM: length 79.4
  TOP w0.135: J3.291 v1(88.44,54.41) ; R108.2 27.62,76.91 arc(27.74,76.73) 27.78,76.51 27.78,73.57 arc(27.74,73.47) 27.65,73.43 v1(27.52,73.43)
  ART03 w0.135: v1(27.52,73.43) 27.71,73.24 arc(27.84,73.05) 27.89,72.82 27.89,72.57 arc(28.13,71.99) 28.7,71.75 32.3,71.75 arc(33.11,71.59) 33.79,71.14 33.89,71.03 arc(34.68,70.51) 35.61,70.33 44.01,70.33 arc(44.27,70.38) 44.49,70.52 44.59,70.63 arc(44.71,70.7) 44.85,70.73 47.45,70.73 arc(48.11,70.6) 48.66,70.23 52.09,66.8 arc(52.96,66.22) 53.99,66.01 63.44,66.01 arc(63.81,66.09) 64.13,66.3 64.23,66.4 arc(64.45,66.55) 64.7,66.6 74.1,66.6 arc(75.01,66.42) 75.78,65.9 79.93,61.75 arc(80.06,61.56) 80.1,61.34 80.1,60.11 arc(80.22,59.52) 80.55,59.02 82.56,57.02 arc(82.6,56.92) 82.56,56.83 arc(82.52,56.73) 82.56,56.63 82.84,56.35 arc(82.94,56.31) 83.03,56.35 arc(83.13,56.39) 83.22,56.35 83.51,56.06 arc(83.55,55.97) 83.51,55.87 arc(83.47,55.78) 83.51,55.68 83.79,55.4 arc(83.89,55.36) 83.99,55.4 arc(84.08,55.44) 84.18,55.4 84.39,55.18 arc(84.8,54.91) 85.28,54.81 85.68,54.81 arc(85.78,54.77) 85.83,54.66 arc(85.87,54.55) 85.98,54.51 86.35,54.51 arc(86.46,54.55) 86.5,54.66 arc(86.55,54.77) 86.65,54.81 87.11,54.81 arc(87.21,54.77) 87.25,54.67 arc(87.29,54.57) 87.39,54.53 87.78,54.53 arc(87.88,54.57) 87.92,54.67 arc(87.97,54.77) 88.06,54.81 88.56,54.81 arc(88.72,54.78) 88.87,54.68 88.89,54.66 arc(88.99,54.52) 89.02,54.35 89.02,54.09 arc(88.97,53.97) 88.86,53.93 88.68,53.93 arc(88.51,53.96) 88.38,54.05 88.37,54.06 arc(88.31,54.2) 88.37,54.33 v1(88.44,54.41)
USB2_OTG0_DP: length 79
  TOP w0.135: J3.293 88.94,54.32 arc(88.88,54.01) 88.7,53.74 v1(88.44,53.48) ; v1(28.36,73.43) 28.22,73.58 arc(28.13,73.71) 28.1,73.87 28.1,76.51 arc(28.14,76.73) 28.26,76.91 R107.2
  ART03 w0.135: v1(88.44,53.48) 88.52,53.56 arc(88.58,53.6) 88.66,53.61 88.86,53.61 arc(89.19,53.75) 89.33,54.09 89.33,54.35 arc(89.27,54.64) 89.11,54.88 89.09,54.91 arc(88.84,55.07) 88.56,55.13 85.28,55.13 arc(84.92,55.2) 84.62,55.4 80.78,59.24 arc(80.51,59.64) 80.42,60.11 80.42,61.34 arc(80.35,61.68) 80.15,61.97 76,66.12 arc(75.13,66.71) 74.1,66.91 64.7,66.91 arc(64.33,66.84) 64.01,66.63 63.91,66.52 arc(63.69,66.38) 63.44,66.33 53.99,66.33 arc(53.08,66.51) 52.31,67.02 48.88,70.45 arc(48.23,70.89) 47.45,71.04 44.85,71.04 arc(44.59,70.99) 44.37,70.85 44.27,70.74 arc(44.15,70.66) 44.01,70.64 35.61,70.64 arc(34.8,70.8) 34.11,71.25 34.01,71.36 arc(33.23,71.88) 32.3,72.07 28.7,72.07 arc(28.35,72.22) 28.2,72.57 28.2,73.17 arc(28.22,73.26) 28.27,73.34 v1(28.36,73.43)
USB2_OTG0_ID: length 5.5
  TOP w0.107: R104.2 77.35,51.2 77.35,53.42 77.44,53.51 J3.247
USB2_OTG0_VBUSDET: length 2.9
  TOP w0.107: J3.249 77.94,53.03 R103.2
USB2_OTG1_DM: length 27.4
  TOP w0.135: J3.287 87.44,56.88 87.53,56.98 87.53,57.23 arc(87.68,57.59) 88.05,57.74 94.61,57.74 arc(95.24,57.48) 95.5,56.84 95.5,41.49 arc(95.55,41.25) 95.69,41.05 95.84,40.9 arc(96.04,40.77) 96.27,40.72 96.32,40.72 arc(96.54,40.76) 96.72,40.89 R132.1
USB2_OTG1_DP: length 27.5
  TOP w0.135: R131.1 96.72,40.24 arc(96.54,40.36) 96.32,40.41 96.27,40.41 arc(95.92,40.48) 95.62,40.68 95.47,40.83 arc(95.26,41.13) 95.19,41.49 95.19,52.36 arc(95.16,52.45) 95.07,52.49 arc(94.98,52.52) 94.95,52.61 94.95,52.9 arc(94.98,52.99) 95.07,53.03 arc(95.16,53.06) 95.19,53.15 95.19,53.44 arc(95.16,53.53) 95.07,53.56 arc(94.98,53.6) 94.95,53.69 94.95,53.98 arc(94.98,54.07) 95.07,54.1 arc(95.16,54.14) 95.19,54.23 95.19,56.84 arc(95.02,57.26) 94.61,57.43 88.05,57.43 arc(87.91,57.37) 87.85,57.23 87.85,56.93 87.94,56.84 J3.289
USB2_OTG1_ID: length 5.4
  TOP w0.107: R137.2 78.44,51.19 J3.251
USB2_OTG1_VBUSDET: length 2.9
  TOP w0.107: J3.253 78.94,53 R136.2
USB3_OTG0_SSRX1N: length 74.4
  TOP w0.135: J3.300 91.19,62.64 arc(91.18,62.57) 91.14,62.51 91.12,62.49 arc(91.08,62.44) 91.07,62.37 91.07,61.64 arc(91.08,61.57) 91.12,61.51 v1(91.19,61.44) ; R113.2 32.71,76.91 arc(32.58,76.73) 32.54,76.51 32.54,76.16 32.54,75.75 arc(32.57,75.59) 32.66,75.45 v1(32.8,75.31)
  ART03 w0.135: v1(91.19,61.44) 91.26,61.51 arc(91.29,61.56) 91.31,61.62 91.31,61.67 arc(91.29,61.75) 91.25,61.81 91.15,61.91 arc(91.04,62.08) 91,62.27 91,64.64 arc(90.96,64.74) 90.85,64.79 arc(90.75,64.83) 90.7,64.94 90.7,65.31 arc(90.75,65.42) 90.85,65.46 arc(90.96,65.5) 91,65.61 91,66.86 arc(90.97,66.99) 90.9,67.1 90.88,67.13 arc(90.77,67.2) 90.64,67.23 90.52,67.23 arc(90.41,67.18) 90.37,67.08 arc(90.32,66.97) 90.22,66.93 89.84,66.93 arc(89.74,66.97) 89.69,67.08 arc(89.65,67.18) 89.55,67.23 89.17,67.23 arc(89.06,67.18) 89.02,67.08 arc(88.98,66.97) 88.87,66.93 88.5,66.93 arc(88.39,66.97) 88.35,67.08 arc(88.3,67.18) 88.2,67.23 87.71,67.23 arc(87.52,67.26) 87.36,67.37 87.31,67.42 arc(87.2,67.47) 87.09,67.42 arc(86.99,67.38) 86.88,67.42 86.62,67.69 arc(86.57,67.79) 86.62,67.9 arc(86.66,68) 86.62,68.11 86.35,68.37 arc(86.25,68.42) 86.14,68.37 arc(86.04,68.33) 85.93,68.37 85.67,68.64 arc(85.62,68.74) 85.67,68.85 arc(85.71,68.95) 85.67,69.06 84.97,69.76 arc(84.2,70.27) 83.29,70.45 55.88,70.45 arc(55.53,70.52) 55.24,70.71 51.45,74.5 arc(50.68,75.02) 49.77,75.2 37.4,75.2 arc(36.81,75.32) 36.31,75.66 36.2,75.76 arc(35.8,76.03) 35.33,76.12 32.91,76.12 arc(32.65,76.02) 32.54,75.76 32.54,75.74 arc(32.58,75.59) 32.67,75.45 v1(32.8,75.31)
USB3_OTG0_SSRX1P: length 75.6
  TOP w0.135: J3.298 90.69,62.57 90.75,62.51 90.75,61.43 arc(90.78,61.28) 90.87,61.15 91.13,60.89 arc(91.18,60.82) 91.19,60.74 v1(91.19,60.63) ; R112.2 32.06,76.91 arc(32.19,76.73) 32.23,76.51 32.23,75.46 arc(32.19,75.36) 32.08,75.31 v1(31.97,75.31)
  ART03 w0.135: v1(91.19,60.63) 91.19,60.75 arc(91.21,60.83) 91.25,60.9 91.5,61.15 arc(91.59,61.28) 91.62,61.43 91.62,61.67 arc(91.58,61.87) 91.47,62.03 91.37,62.13 arc(91.33,62.2) 91.31,62.27 91.31,66.86 arc(91.26,67.11) 91.12,67.32 91.1,67.35 arc(90.89,67.49) 90.64,67.54 87.71,67.54 arc(87.64,67.55) 87.58,67.59 85.19,69.98 arc(84.32,70.56) 83.29,70.76 55.88,70.76 arc(55.65,70.81) 55.47,70.94 51.67,74.73 arc(50.8,75.31) 49.77,75.51 37.4,75.51 arc(36.93,75.61) 36.53,75.88 36.42,75.98 arc(35.92,76.32) 35.33,76.44 32.91,76.44 arc(32.43,76.24) 32.23,75.76 arc(32.2,75.59) 32.11,75.46 v1(31.97,75.31)
USB3_OTG0_SSRX2N: length 76.8
  TOP w0.135: J3.292 89.19,62.65 arc(89.18,62.58) 89.14,62.52 89.12,62.5 arc(89.07,62.43) 89.06,62.36 89.06,61.65 arc(89.07,61.58) 89.12,61.51 v1(89.19,61.44) ; R117.2 25.85,76.91 arc(25.73,76.73) 25.68,76.51 25.68,75.45 arc(25.72,75.35) 25.82,75.31 v1(25.95,75.31)
  ART03 w0.135: v1(89.19,61.44) 89.12,61.51 arc(89.09,61.56) 89.08,61.62 89.08,63.2 arc(89.04,63.38) 88.94,63.54 88.89,63.58 arc(88.85,63.69) 88.89,63.8 arc(88.94,63.91) 88.89,64.02 88.63,64.28 arc(88.52,64.32) 88.42,64.28 arc(88.31,64.23) 88.2,64.28 88.09,64.39 arc(87.94,64.49) 87.76,64.52 87.7,64.52 arc(87.6,64.56) 87.56,64.66 arc(87.52,64.76) 87.42,64.8 87.02,64.8 arc(86.93,64.76) 86.89,64.66 arc(86.85,64.56) 86.75,64.52 86.35,64.52 arc(86.25,64.56) 86.21,64.66 arc(86.17,64.76) 86.08,64.8 85.68,64.8 arc(85.58,64.76) 85.54,64.66 arc(85.5,64.56) 85.4,64.52 85.14,64.52 84.85,64.82 arc(84.7,64.91) 84.53,64.95 84.46,64.95 arc(84.37,64.98) 84.33,65.07 arc(84.29,65.16) 84.2,65.2 83.78,65.2 arc(83.69,65.16) 83.66,65.07 arc(83.62,64.98) 83.53,64.95 83.21,64.95 arc(83.05,64.98) 82.9,65.08 82.85,65.13 arc(82.81,65.23) 82.85,65.32 arc(82.89,65.42) 82.85,65.51 82.56,65.8 arc(82.47,65.84) 82.37,65.8 arc(82.28,65.76) 82.18,65.8 81.9,66.08 arc(81.86,66.18) 81.9,66.28 arc(81.94,66.37) 81.9,66.47 81.61,66.75 arc(81.52,66.79) 81.42,66.75 arc(81.32,66.71) 81.23,66.75 79.93,68.05 arc(79.05,68.64) 78.02,68.84 54.51,68.84 arc(53.6,69.02) 52.82,69.54 52.13,70.23 arc(52.03,70.37) 52,70.54 52,70.86 arc(51.91,71.3) 51.66,71.68 50.72,72.63 arc(49.84,73.21) 48.81,73.41 43.97,73.41 arc(43.41,73.3) 42.94,72.99 42.84,72.88 arc(42.47,72.64) 42.03,72.55 37.77,72.55 arc(37.04,72.69) 36.43,73.11 36.33,73.21 arc(35.61,73.69) 34.76,73.86 31.12,73.86 arc(30.4,74) 29.8,74.4 29.7,74.5 arc(28.99,74.98) 28.16,75.14 26.23,75.14 arc(26.13,75.16) 26.04,75.22 v1(25.95,75.31)
USB3_OTG0_SSRX2P: length 77.1
  TOP w0.135: v1(25.11,75.31) 25.25,75.45 arc(25.34,75.59) 25.37,75.75 25.37,76.51 arc(25.33,76.73) 25.2,76.91 R114.2 ; J3.290 88.69,62.54 88.75,62.48 88.75,61.54 arc(88.8,61.26) 88.96,61.03 89.14,60.85 arc(89.18,60.79) 89.19,60.73 v1(89.19,60.63)
  ART03 w0.135: v1(89.19,60.63) 89.19,60.74 arc(89.18,60.82) 89.13,60.88 88.88,61.13 arc(88.8,61.26) 88.77,61.41 88.77,63.2 arc(88.75,63.26) 88.72,63.32 87.86,64.17 arc(87.82,64.2) 87.76,64.21 85.01,64.21 84.63,64.6 arc(84.59,64.63) 84.53,64.64 83.21,64.64 arc(82.93,64.69) 82.68,64.86 79.71,67.83 arc(78.93,68.35) 78.02,68.53 54.51,68.53 arc(53.48,68.73) 52.6,69.32 51.91,70.01 arc(51.75,70.25) 51.69,70.54 51.69,70.86 arc(51.62,71.18) 51.44,71.46 50.5,72.4 arc(49.72,72.92) 48.81,73.1 43.97,73.1 arc(43.53,73.01) 43.16,72.77 43.06,72.66 arc(42.59,72.35) 42.03,72.24 37.77,72.24 arc(36.93,72.41) 36.21,72.88 36.11,72.99 arc(35.49,73.4) 34.76,73.54 31.12,73.54 arc(30.28,73.71) 29.58,74.18 29.48,74.28 arc(28.87,74.69) 28.16,74.83 26.03,74.83 arc(25.73,74.89) 25.47,75.06 25.22,75.31 v1(25.11,75.31)
USB3_OTG0_SSTX1N: length 74.3
  TOP w0.135: C100.2 30.03,76.91 arc(30.15,76.73) 30.2,76.51 30.2,75.75 arc(30.17,75.59) 30.07,75.45 v1(29.93,75.31) ; v1(90.19,60.63) 90.19,60.75 arc(90.17,60.83) 90.13,60.9 89.88,61.15 arc(89.79,61.28) 89.76,61.43 89.76,62.51 89.69,62.58 J3.294
  ART03 w0.135: v1(90.19,60.63) 90.19,60.75 arc(90.17,60.83) 90.13,60.9 89.87,61.16 arc(89.79,61.28) 89.76,61.43 89.76,64.7 88.87,65.58 arc(88.83,65.62) 88.77,65.63 86.04,65.63 arc(85.76,65.68) 85.51,65.85 85.41,65.95 arc(85.27,66.04) 85.1,66.08 83.74,66.08 arc(83.37,66.15) 83.06,66.36 80.53,68.89 arc(79.9,69.31) 79.16,69.45 54.77,69.45 arc(54.03,69.6) 53.39,70.02 53.09,70.33 arc(52.87,70.65) 52.8,71.03 52.8,71.17 arc(52.75,71.43) 52.6,71.64 51,73.24 arc(50.23,73.76) 49.32,73.94 43.39,73.94 arc(43.03,73.87) 42.73,73.67 42.63,73.57 arc(42.23,73.3) 41.75,73.2 38.19,73.2 arc(37.33,73.37) 36.61,73.86 36.5,73.96 arc(35.88,74.38) 35.14,74.52 30.72,74.52 arc(30.53,74.56) 30.37,74.67 30.2,74.84 30.2,74.96 arc(30.18,75.04) 30.13,75.12 v1(29.93,75.31)
USB3_OTG0_SSTX1P: length 74.6
  TOP w0.135: C99.2 30.68,76.91 arc(30.55,76.73) 30.51,76.51 30.51,75.75 arc(30.54,75.59) 30.63,75.45 v1(30.77,75.31) ; v1(90.19,61.44) 90.12,61.51 arc(90.09,61.56) 90.08,61.62 90.08,62.45 arc(90.09,62.51) 90.12,62.57 90.14,62.58 arc(90.18,62.64) 90.19,62.7 J3.296
  ART03 w0.135: v1(30.77,75.31) 30.64,75.31 arc(30.55,75.27) 30.51,75.18 30.51,74.97 30.59,74.89 arc(30.65,74.85) 30.72,74.84 35.14,74.84 arc(36,74.67) 36.72,74.18 36.83,74.08 arc(37.45,73.66) 38.19,73.52 41.75,73.52 arc(42.11,73.59) 42.41,73.79 42.51,73.89 arc(42.91,74.16) 43.39,74.25 49.32,74.25 arc(50.35,74.05) 51.23,73.46 52.82,71.86 arc(53.04,71.55) 53.11,71.17 53.11,71.03 arc(53.16,70.77) 53.31,70.55 53.61,70.25 arc(54.15,69.89) 54.77,69.77 79.16,69.77 arc(80.02,69.59) 80.75,69.11 81.35,68.51 arc(81.45,68.47) 81.56,68.51 arc(81.67,68.56) 81.78,68.51 82.04,68.25 arc(82.08,68.15) 82.04,68.04 arc(81.99,67.93) 82.04,67.82 82.3,67.56 arc(82.41,67.52) 82.51,67.56 arc(82.62,67.61) 82.73,67.56 82.99,67.3 arc(83.03,67.19) 82.99,67.09 arc(82.95,66.98) 82.99,66.87 83.28,66.58 arc(83.49,66.44) 83.74,66.39 85.1,66.39 arc(85.39,66.33) 85.63,66.17 85.73,66.07 arc(85.88,65.97) 86.04,65.94 87.73,65.94 arc(87.83,65.98) 87.87,66.08 arc(87.91,66.18) 88.01,66.22 88.4,66.22 arc(88.5,66.18) 88.54,66.08 arc(88.58,65.98) 88.68,65.94 88.77,65.94 arc(88.95,65.9) 89.09,65.8 89.21,65.69 arc(89.31,65.65) 89.41,65.69 arc(89.51,65.73) 89.61,65.69 89.88,65.41 arc(89.92,65.31) 89.88,65.21 arc(89.84,65.11) 89.88,65.02 90.07,64.83 90.07,64.18 arc(90.11,64.07) 90.22,64.02 arc(90.33,63.98) 90.37,63.87 90.37,63.5 arc(90.33,63.4) 90.22,63.35 arc(90.11,63.31) 90.07,63.2 90.07,62.83 arc(90.11,62.72) 90.22,62.68 arc(90.33,62.63) 90.37,62.53 90.37,62.16 arc(90.33,62.05) 90.22,62.01 arc(90.11,61.96) 90.07,61.85 90.07,61.64 arc(90.08,61.57) 90.12,61.51 v1(90.19,61.44)
USB3_OTG0_SSTX2N: length 77.7
  TOP w0.135: J3.286 87.69,62.63 87.76,62.56 87.76,61.43 arc(87.79,61.28) 87.87,61.15 88.13,60.89 arc(88.17,60.82) 88.19,60.74 v1(88.19,60.63) ; C102.2 23.13,76.95 arc(23.23,76.81) 23.26,76.64 23.26,75.62 arc(23.24,75.51) 23.18,75.42 v1(23.08,75.31)
  ART03 w0.135: v1(23.08,75.31) 23.14,75.25 arc(23.17,75.2) 23.19,75.14 23.19,74.78 23.67,74.3 arc(24.13,73.99) 24.67,73.88 28.42,73.88 arc(28.56,73.85) 28.68,73.77 29.37,73.08 arc(29.8,72.8) 30.3,72.7 33.95,72.7 arc(34.75,72.54) 35.44,72.08 35.54,71.98 arc(36.32,71.46) 37.25,71.27 42.94,71.27 arc(43.33,71.35) 43.66,71.57 43.76,71.67 arc(43.99,71.83) 44.26,71.88 47.54,71.88 arc(48.45,71.7) 49.23,71.19 52.59,67.82 arc(53.47,67.24) 54.5,67.03 62.93,67.03 arc(63.27,67.1) 63.56,67.29 63.66,67.39 arc(63.85,67.52) 64.07,67.56 76.24,67.56 arc(76.62,67.49) 76.94,67.28 80.75,63.46 arc(81,63.3) 81.29,63.24 83.92,63.24 arc(83.98,63.23) 84.02,63.2 84.39,62.83 87.33,62.83 arc(87.54,62.75) 87.63,62.54 87.63,61.39 88.13,60.89 arc(88.17,60.82) 88.19,60.74 v1(88.19,60.63)
USB3_OTG0_SSTX2P: length 79
  TOP w0.135: v1(23.91,75.31) 23.72,75.31 arc(23.62,75.36) 23.58,75.46 23.58,76.38 arc(23.63,76.65) 23.78,76.87 C101.2 ; J3.288 88.19,62.71 arc(88.18,62.64) 88.14,62.59 88.12,62.57 arc(88.08,62.51) 88.07,62.44 88.07,61.63 arc(88.08,61.57) 88.12,61.51 v1(88.19,61.44)
  ART03 w0.135: v1(23.91,75.31) 23.85,75.38 23.72,75.38 arc(23.64,75.37) 23.58,75.32 23.56,75.3 arc(23.51,75.24) 23.5,75.17 23.5,74.91 23.89,74.52 arc(24.25,74.28) 24.67,74.19 28.42,74.19 arc(28.68,74.14) 28.9,73.99 29.59,73.3 arc(29.92,73.09) 30.3,73.01 33.95,73.01 arc(34.87,72.83) 35.66,72.3 35.76,72.2 arc(36.44,71.74) 37.25,71.58 42.94,71.58 arc(43.21,71.64) 43.44,71.79 43.54,71.9 arc(43.87,72.12) 44.26,72.19 47.54,72.19 arc(48.57,71.99) 49.45,71.41 52.81,68.04 arc(53.59,67.52) 54.5,67.34 62.93,67.34 arc(63.15,67.39) 63.34,67.51 63.44,67.62 arc(63.73,67.81) 64.07,67.88 76.24,67.88 arc(76.74,67.78) 77.16,67.5 77.46,67.19 arc(77.55,67.16) 77.64,67.19 arc(77.72,67.23) 77.81,67.19 78.11,66.9 arc(78.15,66.81) 78.11,66.72 arc(78.08,66.63) 78.11,66.54 78.34,66.31 arc(78.43,66.27) 78.53,66.31 arc(78.63,66.35) 78.72,66.31 79.01,66.03 arc(79.05,65.93) 79.01,65.84 arc(78.97,65.74) 79.01,65.65 79.29,65.36 arc(79.39,65.32) 79.48,65.36 arc(79.58,65.4) 79.67,65.36 79.96,65.08 arc(80,64.98) 79.96,64.89 arc(79.92,64.79) 79.96,64.7 80.24,64.41 arc(80.34,64.37) 80.43,64.41 arc(80.53,64.45) 80.62,64.41 80.91,64.12 arc(80.95,64.03) 80.91,63.93 arc(80.87,63.84) 80.91,63.74 80.97,63.68 arc(81.12,63.59) 81.29,63.55 81.57,63.55 arc(81.66,63.59) 81.7,63.68 arc(81.74,63.77) 81.83,63.8 82.25,63.8 arc(82.34,63.77) 82.37,63.68 arc(82.41,63.59) 82.5,63.55 82.92,63.55 arc(83.01,63.59) 83.05,63.68 arc(83.09,63.77) 83.17,63.8 83.59,63.8 arc(83.68,63.77) 83.72,63.68 arc(83.76,63.59) 83.85,63.55 83.92,63.55 arc(84.1,63.52) 84.24,63.42 84.52,63.14 84.78,63.14 arc(84.88,63.19) 84.92,63.28 arc(84.96,63.38) 85.06,63.42 85.45,63.42 arc(85.55,63.38) 85.59,63.28 arc(85.63,63.19) 85.73,63.14 86.12,63.14 arc(86.22,63.19) 86.26,63.28 arc(86.3,63.38) 86.4,63.42 86.8,63.42 arc(86.9,63.38) 86.94,63.28 arc(86.98,63.19) 87.08,63.14 87.33,63.14 arc(87.76,62.97) 87.94,62.54 87.94,61.52 88.02,61.44 v1(88.19,61.44)
USB3_OTG1_SSRXN: length 55.9
  TOP w0.135: J3.212 69.19,62.6 69.28,62.51 69.28,61.47 arc(69.48,60.51) 70.02,59.7 70.57,59.15 arc(71.44,58.57) 72.47,58.36 91.04,58.36 arc(92.07,58.57) 92.94,59.15 95.48,61.69 arc(95.9,62.31) 96.04,63.05 96.04,63.19 arc(96.17,63.8) 96.51,64.32 96.64,64.45 arc(97.27,64.87) 98.01,65.02 108.51,65.02 arc(109.45,65.2) 110.25,65.74 112.42,67.91 arc(112.62,68.04) 112.84,68.09 113.83,68.09 arc(113.99,68.05) 114.12,67.96 114.15,67.94 arc(114.24,67.8) 114.27,67.64 114.27,67.61 arc(114.24,67.45) 114.15,67.31 v1(114.01,67.17)
  BOTTOM w0.135: R110.2 114.1,68.4 arc(114.23,68.22) 114.27,68 114.27,67.61 arc(114.24,67.45) 114.15,67.31 v1(114.01,67.17)
USB3_OTG1_SSRXP: length 55.9
  TOP w0.135: v1(114.85,67.17) 114.71,67.31 arc(114.61,67.45) 114.58,67.61 114.58,67.64 arc(114.53,67.92) 114.37,68.16 114.35,68.19 arc(114.11,68.34) 113.83,68.4 112.84,68.4 arc(112.5,68.33) 112.2,68.13 110.03,65.96 arc(109.33,65.49) 108.51,65.33 98.01,65.33 arc(97.15,65.16) 96.42,64.67 96.29,64.54 arc(95.88,63.92) 95.73,63.19 95.73,63.05 arc(95.61,62.43) 95.26,61.91 92.72,59.37 arc(91.95,58.86) 91.04,58.67 72.47,58.67 arc(71.56,58.86) 70.79,59.37 70.24,59.92 arc(69.76,60.63) 69.6,61.47 69.6,62.51 69.69,62.6 J3.214
  BOTTOM w0.135: v1(114.85,67.17) 114.71,67.31 arc(114.61,67.45) 114.58,67.61 114.58,68 arc(114.63,68.22) 114.75,68.4 R111.2
USB3_OTG1_SSTXN: length 60.5
  TOP w0.135: v1(118.49,67.18) 118.63,67.32 arc(118.72,67.45) 118.75,67.61 118.75,67.75 arc(118.71,67.96) 118.59,68.15 C97.2 ; v1(110.52,67.99) 110.38,67.85 arc(110.29,67.72) 110.26,67.56 110.26,67.49 arc(110.2,67.18) 110.03,66.92 109.19,66.09 arc(108.93,65.92) 108.63,65.85 97.71,65.85 arc(96.8,65.67) 96.03,65.16 95.64,64.77 arc(95.31,64.28) 95.2,63.7 95.2,63.16 arc(95.13,62.83) 94.95,62.55 92.64,60.25 arc(91.77,59.67) 90.74,59.46 72.02,59.46 arc(71.7,59.52) 71.44,59.7 70.51,60.63 arc(70.34,60.88) 70.28,61.18 70.28,62.51 70.19,62.6 J3.216
  ART03 w0.135: v1(118.49,67.18) 118.63,67.04 arc(118.72,66.9) 118.75,66.74 118.75,66.57 arc(118.58,66.16) 118.18,65.99 111.52,65.99 arc(110.63,66.36) 110.26,67.24 110.26,67.56 arc(110.29,67.72) 110.38,67.85 v1(110.52,67.99)
